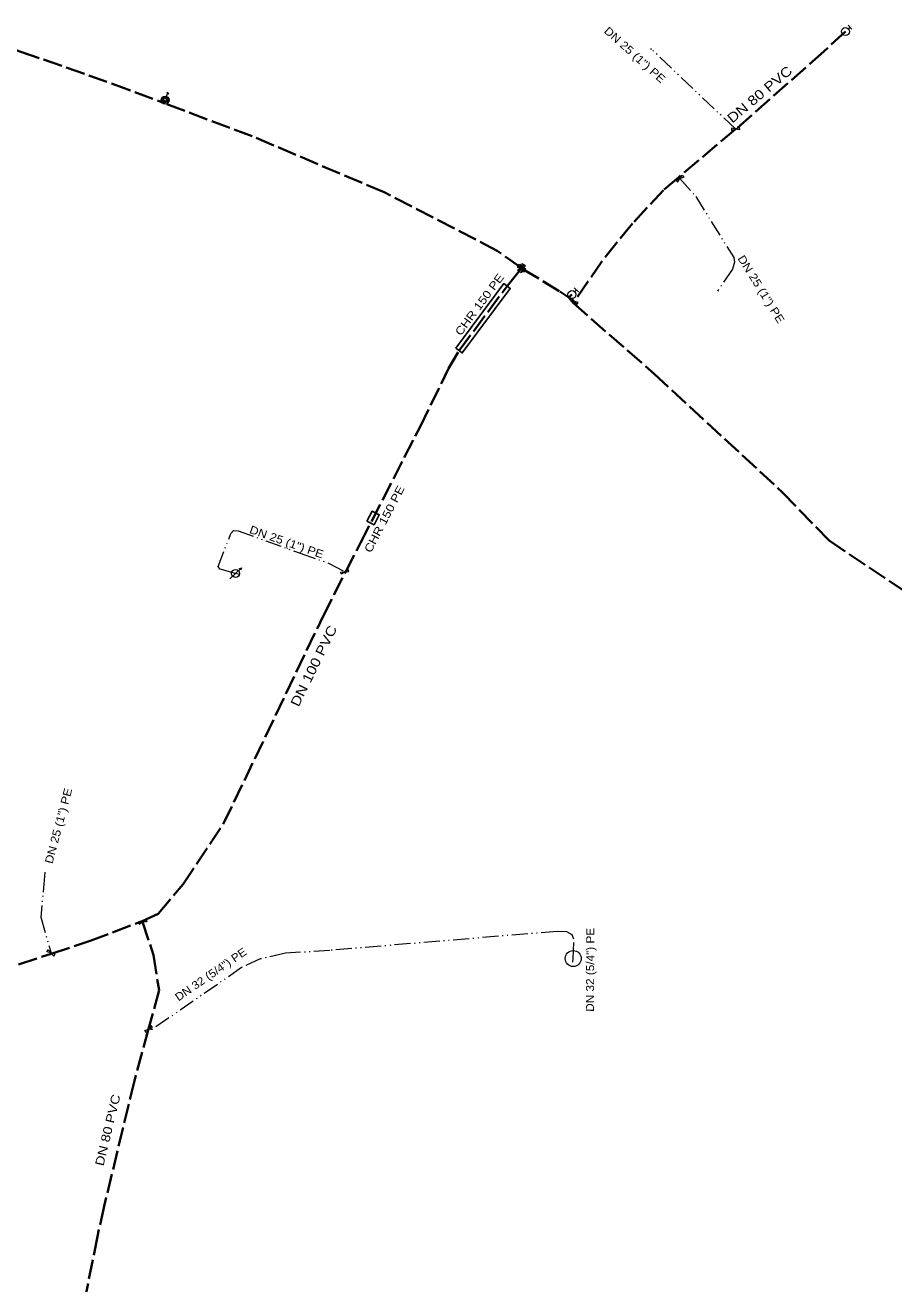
# Model space of a CAD drawing. Extents: x -666789 to -665748, y -1041871 to -1041144.
# Drawn here: x -666079.2 to -665970.6, y -1041592.9 to -1041435.6 of the extents above; entities that cross this region are included whole.
import ezdxf
from ezdxf.enums import TextEntityAlignment as Align

# ---------------------------------------------------------------- set-up
doc = ezdxf.new("R2010")
doc.units = 0
doc.header["$LTSCALE"] = 0.4
doc.linetypes.add('DASH_DOUBLE_DOT', pattern=[9.2, 5, -1.2, 0.3, -1.2, 0.3, -1.2])
doc.linetypes.add('LONG_DASHED', pattern=[7.5, 6, -1.5])
for name, color, linetype, lineweight in [('10', 7, 'Continuous', 13), ('21', 7, 'LONG_DASHED', 35), ('22', 7, 'DASH_DOUBLE_DOT', 35), ('32', 7, 'DASH_DOUBLE_DOT', 13), ('51', 7, 'Continuous', 25)]:
    doc.layers.add(name, color=color, linetype=linetype, lineweight=lineweight)
doc.layers.add('29', color=7, linetype='Continuous')
doc.layers.add('39', color=7, linetype='Continuous')

msp = doc.modelspace()

# ---------------------------------------------------------------- linework, layer by layer
at = {"layer": '10'}
for p, q in [((-665976.304, -1041435.598), (-665975.826, -1041436.109)), ((-665976.284, -1041436.058), (-665976.065, -1041435.853)), ((-666061.359, -1041444.023), (-666061.277, -1041444.205)), ((-666010.544, -1041468.438), (-666010.036, -1041468.92)), ((-666010.496, -1041468.897), (-666010.29, -1041468.679)), ((-666053.628, -1041504.799), (-666052.166, -1041503.435))]:
    msp.add_line(p, q, dxfattribs=at)
for points in [[(-666061.534, -1041444.492), (-666061.359, -1041444.023), (-666061.541, -1041444.106)], [(-666052.441, -1041503.551), (-666052.166, -1041503.435), (-666052.301, -1041503.702)]]:
    msp.add_lwpolyline(points, dxfattribs=at)
for points in [[(-665990.89, -1041448.757), (-665989.912, -1041448.387), (-665989.892, -1041448.686), (-665990.91, -1041448.458)], [(-665997.632, -1041455.205), (-665997.04, -1041454.345), (-665996.852, -1041454.579), (-665997.819, -1041454.971)], [(-666017.693, -1041465.843), (-666016.727, -1041466.237), (-666016.915, -1041466.471), (-666017.505, -1041465.609)], [(-666017.08, -1041465.396), (-666017.42, -1041466.384), (-666017.663, -1041466.209), (-666016.837, -1041465.571)], [(-666016.593, -1041466.029), (-666017.588, -1041465.71), (-666017.418, -1041465.463), (-666016.763, -1041466.276)], [(-666016.919, -1041465.525), (-666017.181, -1041466.535), (-666017.438, -1041466.38), (-666016.662, -1041465.68)], [(-666010.053, -1041470.27), (-666011.047, -1041469.951), (-666010.878, -1041469.704), (-666010.223, -1041470.517)], [(-666038.818, -1041503.609), (-666039.664, -1041504.221), (-666039.762, -1041503.939), (-666038.72, -1041503.891)], [(-666064.956, -1041547.957), (-666064.101, -1041547.359), (-666064.006, -1041547.644), (-666065.05, -1041547.672)], [(-666075.471, -1041551.675), (-666076.482, -1041551.414), (-666076.327, -1041551.157), (-666075.626, -1041551.931)], [(-666063.469, -1041560.61), (-666064.048, -1041561.478), (-666064.24, -1041561.247), (-666063.278, -1041560.841)]]:
    msp.add_lwpolyline(points, close=True, dxfattribs=at)
for centre, radius in [((-665976.6496, -1041436.3997), 0.5), ((-666061.71, -1041444.96), 0.5), ((-666061.71, -1041444.96), 0.35), ((-666061.71, -1041444.96), 0.2), ((-666010.8403, -1041469.2598), 0.5), ((-666052.897, -1041504.117), 0.5), ((-666010.6803, -1041552.2407), 1)]:
    msp.add_circle(centre, radius, dxfattribs=at)
at = {"layer": '21'}
for p, q in [((-665990.371, -1041448.598), (-665997.488, -1041454.585)), ((-666017.21, -1041466.04), (-666017.152, -1041465.958)), ((-666017.152, -1041465.958), (-666017.09, -1041465.87)), ((-666011.225, -1041469.637), (-666010.84, -1041469.26)), ((-666011.225, -1041469.637), (-666010.692, -1041470.306)), ((-666010.55, -1041470.11), (-666010.692, -1041470.306)), ((-666064.56, -1041547.563), (-666064.528, -1041547.658))]:
    msp.add_line(p, q, dxfattribs=at)
for points in [[(-665976.65, -1041436.4), (-665979.355, -1041438.894), (-665990.371, -1041448.598)], [(-666081.493, -1041438.311), (-666079.737, -1041438.912), (-666068.297, -1041442.923), (-666061.852, -1041445.339)], [(-666017.25, -1041465.89), (-666020.192, -1041463.779), (-666034.329, -1041456.483), (-666050.829, -1041449.472), (-666061.852, -1041445.339)], [(-665997.488, -1041454.585), (-665999.405, -1041456.198), (-666003.289, -1041460.397), (-666007.084, -1041465.115), (-666010.55, -1041470.11)], [(-666039.153, -1041503.963), (-666037.278, -1041500.289), (-666029.838, -1041485.79), (-666026.261, -1041478.515), (-666024.949, -1041476.269), (-666018.953, -1041468.2), (-666017.21, -1041466.04)], [(-666017.152, -1041465.958), (-666017.25, -1041465.89), (-666017.25, -1041465.89)], [(-666017.152, -1041465.958), (-666017.05, -1041466.03), (-666017.05, -1041466.03)], [(-666017.05, -1041466.03), (-666012.347, -1041468.886), (-666011.225, -1041469.637)], [(-666010.692, -1041470.306), (-666000.561, -1041479.168), (-665984.507, -1041493.997), (-665978.659, -1041500.014), (-665969.396, -1041506.253), (-665963.153, -1041510.77), (-665955.078, -1041516.429), (-665927.46, -1041533.264), (-665915.073, -1041536.127), (-665901.627, -1041536.815), (-665895.923, -1041536.314), (-665889.116, -1041535.749), (-665877.132, -1041534.678), (-665866.151, -1041533.637), (-665857.888, -1041532.608), (-665846.906, -1041531.169), (-665831.701, -1041528.535)], [(-666064.56, -1041547.563), (-666062.571, -1041546.662), (-666059.466, -1041542.945), (-666054.399, -1041535.387), (-666041.965, -1041509.473), (-666039.153, -1041503.963)], [(-666075.949, -1041551.64), (-666071.08, -1041550.032), (-666064.56, -1041547.563)], [(-666064.528, -1041547.658), (-666063.144, -1041551.84), (-666062.472, -1041556.2), (-666063.784, -1041561.037)], [(-666116.766, -1041564.823), (-666104.583, -1041560.725), (-666085.73, -1041554.871), (-666075.949, -1041551.64)], [(-666063.784, -1041561.037), (-666065.546, -1041567.536), (-666069.329, -1041583.189), (-666070.168, -1041586.963), (-666072.131, -1041596.753), (-666072.425, -1041599.815), (-666072.802, -1041607.076), (-666072.336, -1041612.448), (-666070.066, -1041621.848)]]:
    msp.add_lwpolyline(points, dxfattribs=at)
at = {"layer": '22'}
msp.add_line((-666061.852, -1041445.339), (-666061.71, -1041444.96), dxfattribs=at)
at = {"layer": '32'}
for p, q in [((-666000.875, -1041438.625), (-666000.994, -1041438.512)), ((-665990.401, -1041448.572), (-666000.875, -1041438.625)), ((-665990.371, -1041448.598), (-665990.401, -1041448.572)), ((-665997.488, -1041454.585), (-665997.336, -1041454.775)), ((-665992.545, -1041468.711), (-665992.628, -1041468.835)), ((-666052.415, -1041504.248), (-666052.897, -1041504.117)), ((-666039.241, -1041503.915), (-666039.153, -1041503.963)), ((-666076.758, -1041541.454), (-666076.802, -1041541.953)), ((-666075.977, -1041551.544), (-666075.949, -1041551.64)), ((-666010.717, -1041552.694), (-666010.68, -1041552.241)), ((-666063.758, -1041561.044), (-666063.784, -1041561.037))]:
    msp.add_line(p, q, dxfattribs=at)
for points in [[(-665997.336, -1041454.775), (-665995.366, -1041457.005), (-665990.604, -1041464.642), (-665990.519, -1041465.218), (-665990.776, -1041466.073), (-665992.545, -1041468.711)], [(-666052.897, -1041504.117), (-666054.85, -1041503.587), (-666055.086, -1041503.256), (-666053.493, -1041499.138), (-666053.141, -1041498.76), (-666052.593, -1041498.799), (-666044.844, -1041501.575), (-666041.194, -1041502.855), (-666039.241, -1041503.915)], [(-666076.802, -1041541.953), (-666077.258, -1041547.079), (-666075.977, -1041551.544)], [(-666010.68, -1041552.241), (-666010.585, -1041549.81), (-666010.813, -1041549.285), (-666011.486, -1041548.919), (-666012.7, -1041548.85), (-666041.102, -1041551.225), (-666046.668, -1041551.59), (-666049.812, -1041552.291), (-666052.15, -1041553.377), (-666063.324, -1041561.103), (-666063.501, -1041561.121), (-666063.758, -1041561.044)]]:
    msp.add_lwpolyline(points, dxfattribs=at)
at = {"layer": '51'}
for points in [[(-666025.35, -1041475.971), (-666019.354, -1041467.902), (-666018.552, -1041468.498), (-666024.548, -1041476.567)], [(-666036.474, -1041497.577), (-666035.82, -1041496.327), (-666034.934, -1041496.79), (-666035.588, -1041498.04)]]:
    msp.add_lwpolyline(points, close=True, dxfattribs=at)

# ---------------------------------------------------------------- texts
at = {"layer": '29', "width": 1.2}
for s, rotation, p in [('DN 80 PVC', 40.073, (-665990.793, -1041447.909)), ('DN 100 PVC', 63.817, (-666045.025, -1041520.879))]:
    msp.add_text(s, height=1.2, rotation=rotation, dxfattribs=at).set_placement(p)
msp.add_text('DN 80 PVC', height=1.1, rotation=76.413, dxfattribs=at).set_placement((-666068.3536, -1041573.8082), align=Align.CENTER)
at = {"layer": '39'}
for s, rotation, width, p in [('DN 25 (1") PE', 318.127, 1.15, (-666003.3077, -1041439.6766)), ('DN 25 (1") PE', 301.945, 1.15, (-665987.609, -1041468.8564)), ('DN 25 (1") PE', 340.672, 1.15, (-666046.6835, -1041500.6462)), ('DN 25 (1") PE', 75.153, 1.15, (-666074.5631, -1041535.7871)), ('DN 32 (5/4") PE', 89.721, 1.1, (-666008.0683, -1041553.6534)), ('DN 32 (5/4") PE', 34.661, 1.1, (-666055.7194, -1041554.6349))]:
    msp.add_text(s, height=1, rotation=rotation, dxfattribs=dict(at, width=width)).set_placement(p, align=Align.CENTER)
at = {"layer": '51', "width": 1.2}
for rotation, p in [(53.384, (-666022.0043, -1041470.8092)), (62.381, (-666033.8551, -1041497.5498))]:
    msp.add_text('CHR 150 PE', height=1, rotation=rotation, dxfattribs=at).set_placement(p, align=Align.CENTER)

doc.saveas('drawing.dxf')
